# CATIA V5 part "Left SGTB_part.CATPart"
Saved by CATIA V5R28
Part number: Left SGTB_part
Definition: design
Nomenclature: Left SGTB_part
Source: Unknown
Bounding box of the stored display mesh (mm): x -22.35 to 22.35, y -22.35 to 22.35, z -3.582 to 0
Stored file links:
  D:\paraturbo-cad\STEP\Turbocompressor_for_Christophe\Left SGTB_part.CATPart
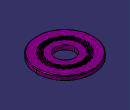
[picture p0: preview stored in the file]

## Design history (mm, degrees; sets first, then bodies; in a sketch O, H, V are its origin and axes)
Body1 "MANIFOLD_SOLID_BREP #14326" (main body)
  Solid1: solid without history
